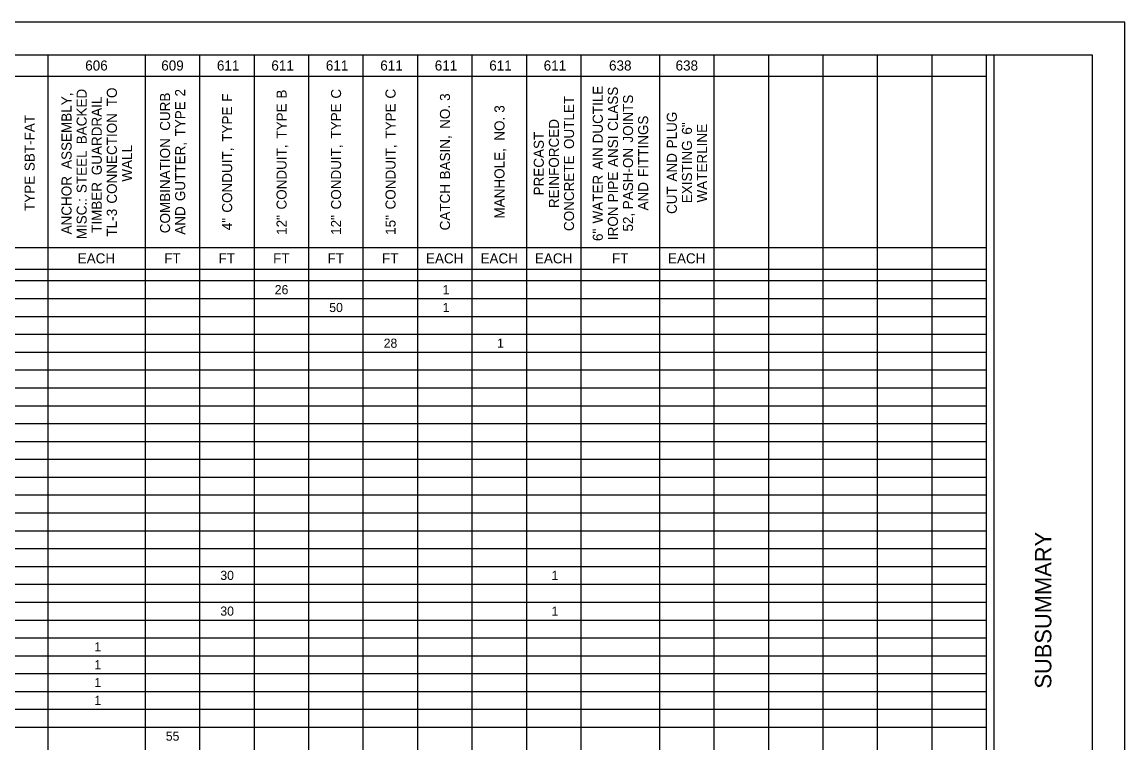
# Model space of a CAD drawing. Extents: x 0 to 34, y 0 to 22.
# Drawn here: x 17.14 to 34, y 10.98 to 22 of the extents above; entities that cross this region are included whole.
import ezdxf

# ---------------------------------------------------------------- set-up
doc = ezdxf.new("R2010")
doc.units = 0
for name, color, linetype in [('SH_Border', 7, 'Continuous'), ('SH_Cut_Line', 7, 'Continuous'), ('SH_Data', 7, 'Continuous')]:
    doc.layers.add(name, color=color, linetype=linetype)

msp = doc.modelspace()

# ---------------------------------------------------------------- linework, layer by layer
at = {"layer": 'SH_Border'}
msp.add_line((32, 0.5), (32, 21.5), dxfattribs=at)
msp.add_lwpolyline([(1.5, 21.5), (33.5, 21.5), (33.5, 0.5), (1.5, 0.5)], close=True, dxfattribs=at)
at = {"layer": 'SH_Cut_Line'}
msp.add_lwpolyline([(0, 0), (34, 0), (34, 22), (0, 22)], close=True, dxfattribs=at)
at = {"layer": 'SH_Data'}
for p, q in [((1.5, 21.5), (31.885, 21.5)), ((17.539, 0.506), (17.539, 21.5)), ((19.027, 0.506), (19.027, 21.5)), ((19.859, 0.506), (19.859, 21.5)), ((20.692, 0.506), (20.692, 21.5)), ((21.525, 0.506), (21.525, 21.5)), ((22.357, 0.506), (22.357, 21.5)), ((23.19, 0.506), (23.19, 21.5)), ((24.022, 0.506), (24.022, 21.5)), ((24.855, 0.506), (24.855, 21.5)), ((25.688, 0.506), (25.688, 21.5)), ((26.889, 0.506), (26.889, 21.5)), ((27.722, 0.506), (27.722, 21.5)), ((28.554, 0.506), (28.554, 21.5)), ((29.387, 0.506), (29.387, 21.5)), ((30.22, 0.506), (30.22, 21.5)), ((31.052, 0.506), (31.052, 21.5)), ((31.885, 0.506), (31.885, 21.5)), ((9.39, 21.172), (31.885, 21.172)), ((9.39, 18.552), (31.885, 18.552)), ((1.5, 18.224), (31.885, 18.224)), ((8.557, 18.224), (31.885, 18.224)), ((1.5, 18.047), (31.885, 18.047)), ((1.5, 17.774), (31.885, 17.774)), ((1.5, 17.501), (31.885, 17.501)), ((1.5, 17.228), (31.885, 17.228)), ((1.5, 16.955), (31.885, 16.955)), ((1.5, 16.682), (31.885, 16.682)), ((1.5, 16.409), (31.885, 16.409)), ((1.5, 16.136), (31.885, 16.136)), ((1.5, 15.863), (31.885, 15.863)), ((1.5, 15.59), (31.885, 15.59)), ((1.5, 15.317), (31.885, 15.317)), ((1.5, 15.044), (31.885, 15.044)), ((1.5, 14.771), (31.885, 14.771)), ((1.5, 14.498), (31.885, 14.498)), ((1.5, 14.225), (31.885, 14.225)), ((1.5, 13.952), (31.885, 13.952)), ((1.5, 13.679), (31.885, 13.679)), ((1.5, 13.406), (31.885, 13.406)), ((1.5, 13.133), (31.885, 13.133)), ((1.5, 12.86), (31.885, 12.86)), ((1.5, 12.587), (31.885, 12.587)), ((1.5, 12.314), (31.885, 12.314)), ((1.5, 12.041), (31.885, 12.041)), ((1.5, 11.768), (31.885, 11.768)), ((1.5, 11.495), (31.885, 11.495)), ((1.5, 11.222), (31.885, 11.222))]:
    msp.add_line(p, q, dxfattribs=at)

# ---------------------------------------------------------------- texts
for s, height, p in [('606', 0.154, (18.107, 21.259)), ('609', 0.154, (19.269, 21.259)), ('611', 0.154, (20.12, 21.259)), ('611', 0.154, (20.952, 21.259)), ('611', 0.154, (21.785, 21.259)), ('611', 0.154, (22.617, 21.259)), ('611', 0.154, (23.45, 21.259)), ('611', 0.154, (24.283, 21.259)), ('611', 0.154, (25.115, 21.259)), ('638', 0.154, (26.114, 21.259)), ('638', 0.154, (27.131, 21.259)), ('EACH', 0.154, (17.992, 18.311)), ('FT', 0.154, (19.314, 18.311)), ('FT', 0.154, (20.146, 18.311)), ('FT', 0.154, (20.979, 18.311)), ('FT', 0.154, (21.812, 18.311)), ('FT', 0.154, (22.644, 18.311)), ('EACH', 0.154, (23.316, 18.311)), ('EACH', 0.154, (24.149, 18.311)), ('EACH', 0.154, (24.981, 18.311)), ('FT', 0.154, (26.159, 18.311)), ('EACH', 0.154, (27.015, 18.311)), ('26', 0.14, (21.004, 17.84)), ('1', 0.14, (23.57, 17.84)), ('50', 0.14, (21.837, 17.567)), ('1', 0.14, (23.57, 17.567)), ('28', 0.14, (22.669, 17.021)), ('1', 0.14, (24.402, 17.021)), ('30', 0.14, (20.172, 13.472)), ('1', 0.14, (25.235, 13.472)), ('30', 0.14, (20.172, 12.926)), ('1', 0.14, (25.235, 12.926)), ('1', 0.14, (18.246, 12.38)), ('1', 0.14, (18.246, 12.107)), ('1', 0.14, (18.246, 11.834)), ('1', 0.14, (18.246, 11.561)), ('55', 0.14, (19.338, 11.015))]:
    msp.add_text(s, height=height, dxfattribs=at).set_placement(p)
for s, height, p in [(' BACKED', 0.154, (18.129, 20.075)), (' TO', 0.154, (18.591, 20.656)), (' CURB', 0.154, (19.404, 20.281)), (' 2', 0.154, (19.635, 20.805)), (' B', 0.154, (21.185, 20.773)), (' C', 0.154, (22.018, 20.773)), (' C', 0.154, (22.851, 20.773)), (' DUCTILE', 0.154, (26.019, 20.089)), (' CLASS', 0.154, (26.25, 20.279)), (' ASSEMBLY,', 0.154, (17.898, 19.698)), (' GUARDRAIL', 0.154, (18.36, 19.602)), (' TYPE', 0.154, (19.635, 20.194)), (' F', 0.154, (20.353, 20.725)), (' TYPE', 0.154, (21.185, 20.161)), (' TYPE', 0.154, (22.018, 20.162)), (' TYPE', 0.154, (22.851, 20.162)), (' 3', 0.154, (23.683, 20.738)), (' OUTLET', 0.154, (25.579, 20.002)), (' JOINTS', 0.154, (26.481, 20.1)), (' SBT-FAT', 0.154, (17.334, 19.664)), (' CONNECTION', 0.154, (18.591, 19.167)), (' TYPE', 0.154, (20.353, 20.113)), (' NO.', 0.154, (23.683, 20.31)), (' 3', 0.154, (24.516, 20.557)), (' PLUG', 0.154, (27.151, 20.012)), (' NO.', 0.154, (24.516, 20.129)), ('REINFORCED', 0.154, (25.348, 19.156)), (' FITTINGS', 0.154, (26.712, 19.575)), (' 6"', 0.154, (27.382, 20.222)), ('WATERLINE', 0.154, (27.613, 19.242)), (' BASIN,', 0.154, (23.683, 19.537)), ('PRECAST', 0.154, (25.117, 19.35)), (' ANSI', 0.154, (26.25, 19.727)), ('WALL', 0.154, (18.822, 19.56)), ('COMBINATION', 0.154, (19.404, 18.772)), (' GUTTER,', 0.154, (19.635, 19.206)), (' CONDUIT,', 0.154, (20.353, 19.029)), (' CONDUIT,', 0.154, (21.185, 19.077)), (' CONDUIT,', 0.154, (22.018, 19.078)), (' CONDUIT,', 0.154, (22.851, 19.078)), (' AIN', 0.154, (26.019, 19.684)), ('EXISTING', 0.154, (27.382, 19.231)), (' STEEL', 0.154, (18.129, 19.328)), ('MANHOLE,', 0.154, (24.516, 18.997)), ('CONCRETE', 0.154, (25.579, 18.806)), (' PASH-ON', 0.154, (26.481, 19.081)), (' AND', 0.154, (27.151, 19.505)), ('TYPE', 0.154, (17.334, 19.112)), ('ANCHOR', 0.154, (17.898, 18.754)), (' WATER', 0.154, (26.019, 18.864)), (' PIPE', 0.154, (26.25, 19.187)), ('TIMBER', 0.154, (18.36, 18.778)), ('CATCH', 0.154, (23.683, 18.816)), ('AND', 0.154, (26.712, 19.12)), ('CUT', 0.154, (27.151, 19.067)), ('MISC.:', 0.154, (18.129, 18.68)), ('TL-3', 0.154, (18.591, 18.722)), ('AND', 0.154, (19.635, 18.75)), ('IRON', 0.154, (26.25, 18.667)), ('52,', 0.154, (26.481, 18.798)), ('4"', 0.154, (20.353, 18.818)), ('12"', 0.154, (21.185, 18.747)), ('12"', 0.154, (22.018, 18.747)), ('15"', 0.154, (22.851, 18.747)), ('6"', 0.154, (26.019, 18.653)), ('SUBSUMMARY', 0.25, (32.875, 11.811))]:
    msp.add_text(s, height=height, rotation=90, dxfattribs=at).set_placement(p)

doc.saveas('drawing.dxf')
